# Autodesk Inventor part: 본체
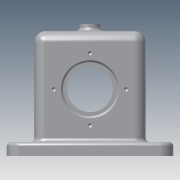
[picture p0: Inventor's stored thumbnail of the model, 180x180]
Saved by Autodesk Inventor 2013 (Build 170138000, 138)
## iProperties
Created: 2018-11
Part Number: 본체
Material: 알루미늄 6061
Document SubType Name: Modeling
Designer: Administrator
Density: 2.71 g/cm^3
Mass: 1021.68 g
Surface Area: 775.693 cm^2
Volume: 377.005 cm^3
Author: Administrator
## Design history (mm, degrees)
sketch "스케치1"
  geometry: L1 (-50, -60)-(50, -60); L2 (60, -50)-(60, 50); L3 (50, 60)-(-50, 60); L4 (-60, 50)-(-60, -50); L5 (-60, -60)-(60, 60); L6 (60, -60)-(-60, 60); L7 (-32, -40)-(32, -40); L8 (40, -32)-(40, 32); L9 (32, 40)-(-32, 40); L10 (-40, 32)-(-40, -32); L11 (-40, -40)-(40, 40); L12 (40, -40)-(-40, 40); A1 r 10 centre (-50, 50) between (-50, 60) and (-60, 50); A2 r 10 centre (-50, -50) between (-60, -50) and (-50, -60); A3 r 10 centre (50, 50) between (60, 50) and (50, 60); A4 r 10 centre (50, -50) between (50, -60) and (60, -50); A5 r 8 centre (-32, 32) between (-32, 40) and (-40, 32); A6 r 8 centre (-32, -32) between (-40, -32) and (-32, -40); A7 r 8 centre (32, -32) between (32, -40) and (40, -32); A8 r 8 centre (32, 32) between (40, 32) and (32, 40); 1 further point
  constraints: 24 end point, 16 point on circle, 16 point on line, 16 tangent, 8 centre point, 6 equal radius, 4 midpoint, 4 parallel, 2 horizontal, 2 perpendicular
  dimensions: "d0" = 120 distance of L6.end L5.end; "d1" = 120 distance of L5.end L6.start; "d2" = 80 distance of L11.end L12.end; "d3" = 80 distance of L12.start L11.end; "d4" = 10 radius of A1; "d5" = 8 radius of A5
extrude "돌출1" new body sketch "스케치1" distance "d6" = 10; taper "d7" = 0 deg
extrude "돌출2" join sketch "스케치1" distance "d8" = 90; taper "d9" = 0 deg
sketch "스케치2"
  geometry: L1 (-20, -30)-(20, -30); L2 (23, -27)-(23, 27); L3 (20, 30)-(-20, 30); L4 (-23, 27)-(-23, -27); L5 (-23, -30)-(23, 30); L6 (23, -30)-(-23, 30); A1 r 3 centre (-20, 27) between (-20, 30) and (-23, 27); A2 r 3 centre (20, 27) between (23, 27) and (20, 30); A3 r 3 centre (20, -27) between (20, -30) and (23, -27); A4 r 3 centre (-20, -27) between (-23, -27) and (-20, -30); 1 further point
  constraints: 12 end point, 8 point on circle, 8 point on line, 8 tangent, 4 centre point, 3 equal radius, 2 midpoint, 2 parallel, 1 horizontal, 1 perpendicular
  dimensions: "d10" = 46 distance of L5.end L6.end; "d12" = 60 distance of L6.start L5.end; "d13" = 3 radius of A1
extrude "돌출3" cut sketch "스케치2" distance "d14" = 80; taper "d15" = 0 deg
sketch "스케치3"
  geometry: C1 r 7.5 at (0, 0); 1 further point
  constraints: 1 centre point, 1 coincident
  dimensions: "d16" = 15 diameter of C1
extrude "돌출4" join sketch "스케치3" distance "d17" = 5; taper "d18" = 0 deg
sketch "스케치4"
  geometry: L1 (10, -18)-(10, 82) reference; 3 further points
  constraints: 1 horizontal alignment, 1 midpoint
  dimensions: "d19" = 48 distance from line of L1 point (-38, 32)
hole "구멍1" sketch "스케치4" at (-38, 32) diameter "d20" = 33; stored, may be unused: countersink angle "d24" = 90 deg, drill point angle "d26" = 118 deg; dims "d21" = 6, "d22" = 40, "d23" = 14, "d25" = 8
sketch "스케치5" dims "d27" = 52
  geometry: C1 r 20 at (-38, 32) reference; 3 further points
  constraints: 2 horizontal alignment, 1 coincident, 2 other
hole "구멍2" sketch "스케치5" at (-64, 32) diameter "d29" = 3.242; stored, may be unused: countersink angle "d33" = 90 deg, drill point angle "d35" = 118 deg; dims "d30" = 8, "d31" = 40, "d32" = 14, "d34" = 10
sketch "스케치6" dims "d46" = 10, "d53" = 10
  geometry: L1 (-32, 40)-(32, 40) reference; L2 (40, 32)-(40, -32) reference; L3 (32, -40)-(-32, -40) reference; L4 (-40, -32)-(-40, 32) reference; L5 (-60, 50)-(-60, -50) reference; L6 (-50, -60)-(50, -60) reference; L7 (-40, 0)-(40, 0); L8 (0, -40)-(0, 40); C1 r 3.3 at (-50, -50); C2 r 3.3 at (-50, -25); C3 r 3.3 at (-50, 0); C4 r 3.3 at (-50, 25); C5 r 3.3 at (-50, 50); C6 r 3.3 at (-40, -50); C7 r 3.3 at (-30, -50); C8 r 3.3 at (-20, -50); C9 r 3.3 at (-10, -50); C10 r 3.3 at (0, -50); C11 r 3.3 at (10, -50); C12 r 3.3 at (20, -50); C13 r 3.3 at (30, -50); C14 r 3.3 at (40, -50); C15 r 3.3 at (50, -50); C16 r 3.3 at (30, 50); C17 r 3.3 at (40, 50); C18 r 3.3 at (20, 50); C19 r 3.3 at (10, 50); C20 r 3.3 at (0, 50); C21 r 3.3 at (-10, 50); C22 r 3.3 at (-20, 50); C23 r 3.3 at (-30, 50); C24 r 3.3 at (-40, 50); C25 r 3.3 at (50, 25); C26 r 3.3 at (50, 0); C27 r 3.3 at (50, -25); A1 r 10 centre (-50, -50) between (-60, -50) and (-50, -60) reference; 1 further point
  constraints: 27 centre point, 12 symmetric about line, 4 end point, 4 midpoint, 1 coincident, 1 horizontal, 1 vertical, 40 other
  dimensions: "d39" = 6.6 diameter of C1; "d43" = 25 distance of C1.centre C2.centre; "d50" = 10 distance of C1.centre C6.centre
extrude "돌출5" cut sketch "스케치6" stored distance "d55" = 5; taper "d56" = 0 deg
chamfer "모따기1" distance "d57" = 1; stored, may be unused: second distance "d58" = 2, angle "d59" = 45 deg
hole "구멍3" diameter "d62" = 4.917; stored, may be unused: countersink angle "d66" = 90 deg, drill point angle "d68" = 118 deg; dims "d60" = 10, "d61" = 10, "d63" = 8, "d64" = 40, "d65" = 14, "d67" = 10
fillet "모깎기1" dims "d69" = 3
fillet "모깎기2" dims "d70" = 0.6
fillet "모깎기3" dims "d71" = 8
sketch "스케치8"
  geometry: L1 (0, 69)-(64, 69) reference; L2 (-18, -13)-(82, -13) reference; 3 further points
  constraints: 1 midpoint, 1 vertical alignment, 1 other
  dimensions: "d72" = 48 distance from line of L2 point (32, 35)
feature "엠보싱1" sketch "스케치8" dims "d0" = 120, "d1" = 120, "d2" = 80, "d3" = 80, "d4" = 10, "d5" = 8, "d73" = 0.5, "d74" = 0
node "솔리드1"
pattern_circular "원형 패턴1" dims angle "d37" = 360 deg
mirror "대칭1"
